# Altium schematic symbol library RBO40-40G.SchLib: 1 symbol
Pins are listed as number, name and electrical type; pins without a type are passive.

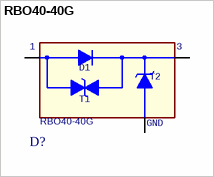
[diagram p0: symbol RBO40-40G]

## RBO40-40G
designator D?
footprint ST_D2PAK-CLIP
pins: 1, 3, TAB GND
